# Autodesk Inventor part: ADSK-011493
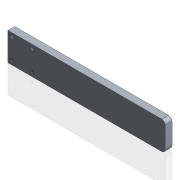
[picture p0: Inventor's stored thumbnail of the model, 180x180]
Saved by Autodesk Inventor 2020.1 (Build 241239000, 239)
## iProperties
Created: 2000-02
Part Number: ADSK-011493
Material: Pearson Aluminium
Description: PLT-04,FA,AX,05,110,020,3333,CORNER_PUSH_MANDREL
Document SubType Name: Modeling
Designer: cmcgourin
Density: 2.71 g/cm^3
Appearance: Pearson-Aluminum
Mass: 445.784 g
Surface Area: 369.175 cm^2
Volume: 164.496 cm^3
Control State: 0
Checked Out: False
Master: False
Shininess: 35.0
Length Units: 11269
Angle Units: 11279
Time Units: 11290
Mass Units: 11283
Length Display Precision: 3
Angle Display Precision: 2
Compacted: True
material desc: FLAT,ALUM,0.500X02.000
Cutlength: 11
Material_Number: A084907
Dimensions: 280x50x12 mm
Mass: 0,446 kg
Density: 2.71
Volumn: 178.00195629436115
Area: 374.89721610676116
PropertySet Name: Model Information
Author: cmcgourin
Revision Number: -
Title: PLT-04,FA,AX,05,110,020,3333,CORNER_PUSH_MANDREL
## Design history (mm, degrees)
node "Solide1"
  node "Extrusion1" dims "d2" = 12, "d3" = 0
  node "Fillet1" dims "d4" = 6.35
  node "Hole1" dims "d5" = 6.6, "d6" = 11, "d7" = 6.8, "d8" = 60 deg, "d9" = 19.05, "d10" = 118 deg, "d14" = 6
sketch "Sketch1"
  geometry: L1 (-140, 25)-(140, 25); L2 (140, 25)-(140, -25); L3 (140, -25)-(-140, -25); L4 (-140, -25)-(-140, 25); 3 further points
  constraints: 8 end point, 2 midpoint, 2 parallel, 1 horizontal, 1 horizontal alignment, 1 perpendicular, 1 vertical alignment
  dimensions: "d0" = 50 distance of L1.end L2.end; "d1" = 280 distance of L1.start L1.end
sketch "Sketch2"
  geometry: L1 (97, 18)-(133, 18); L2 (133, 18)-(133, -18); L3 (133, -18)-(97, -18); L4 (97, -18)-(97, 18); L5 (140, 25)-(140, -25) reference; 2 further points
  constraints: 8 end point, 2 midpoint, 2 parallel, 1 horizontal, 1 horizontal alignment, 1 perpendicular
  dimensions: "d11" = 7 distance between parallel lines of L5 L2; "d12" = 36 distance of L1.start L1.end; "d13" = 36 distance of L3.end L1.start (= d12)
node "Corps solides"
node "Corps surfaciques"
